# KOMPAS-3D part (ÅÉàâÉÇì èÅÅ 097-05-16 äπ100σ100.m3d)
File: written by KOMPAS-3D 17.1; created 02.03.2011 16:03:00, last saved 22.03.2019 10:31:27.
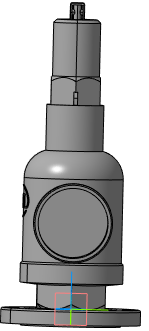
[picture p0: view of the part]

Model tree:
1. Плоскость XY
2. Плоскость ZX
3. Плоскость ZY
4. Ось X
5. Ось Y
6. Ось Z
7. Начало координат
8. Операция без истории:2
